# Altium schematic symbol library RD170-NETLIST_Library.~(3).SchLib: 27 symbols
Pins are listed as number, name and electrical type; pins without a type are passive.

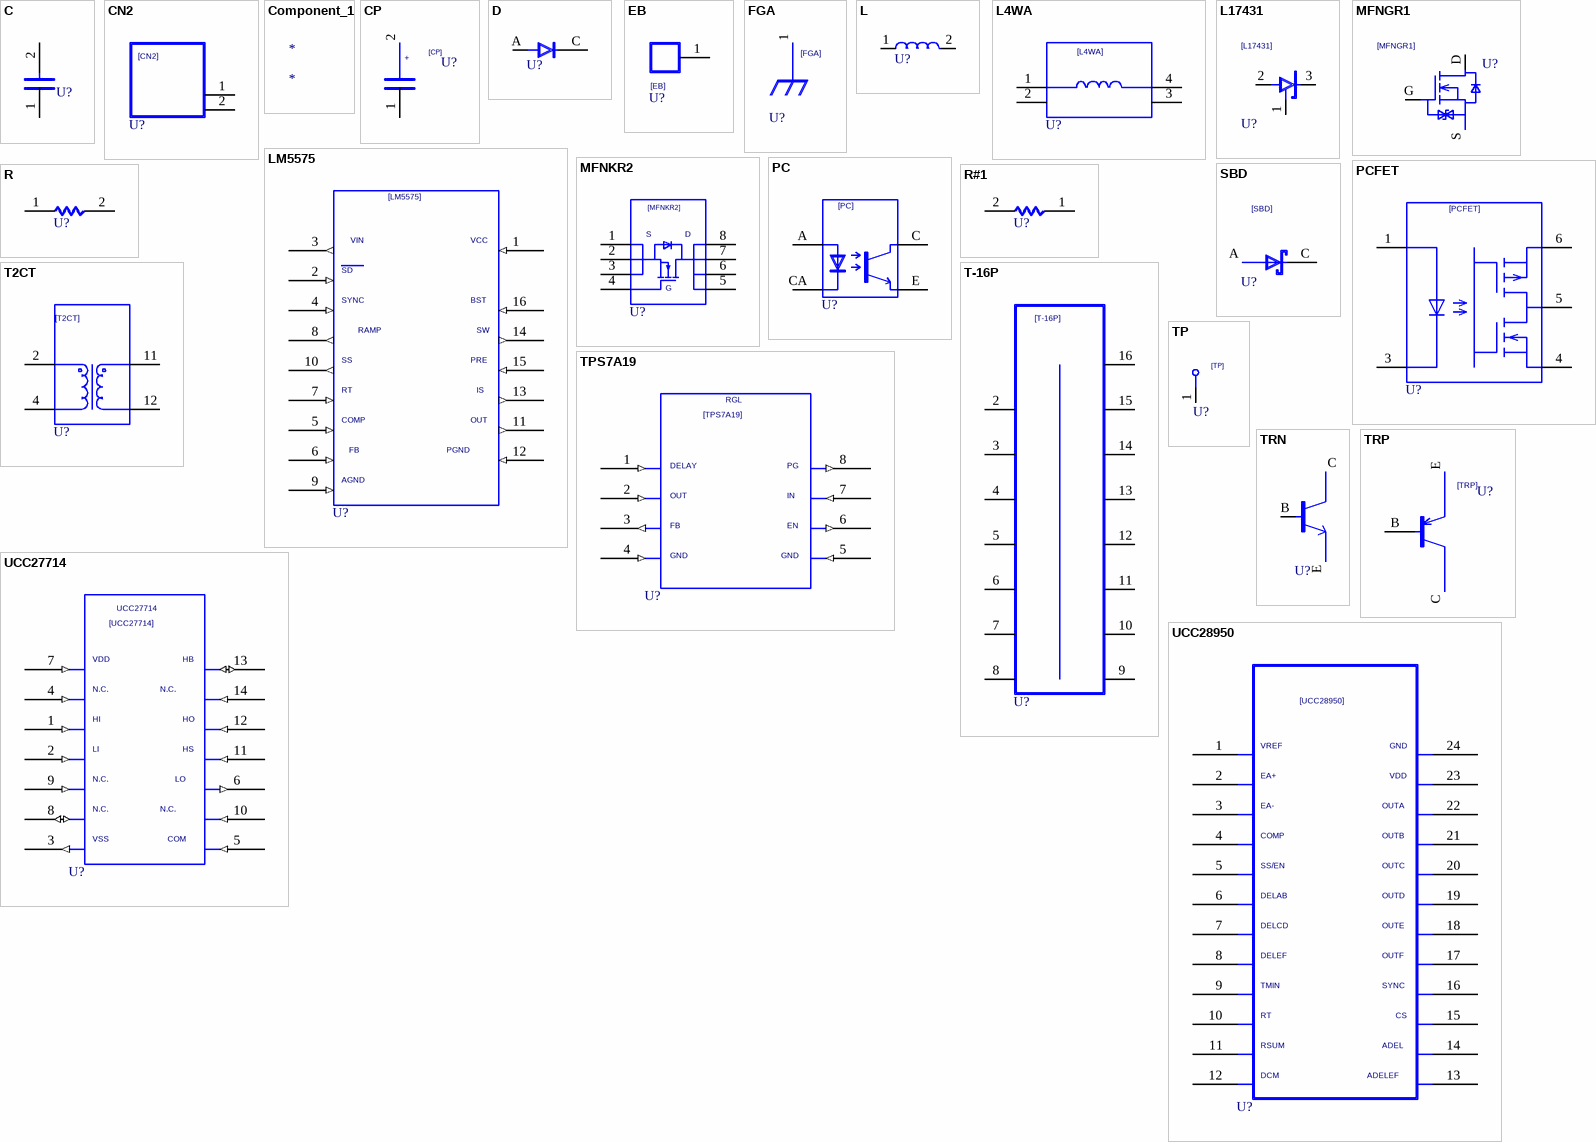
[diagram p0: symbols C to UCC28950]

## C
designator U?  (value not drawn)
OriginalSymbolOrigin: (2540,7620); Altium-Right: 20; Altium-Bottom: 10
pins: 1, 2

## CN2
designator U?  (value not drawn)
OriginalSymbolOrigin: (2540,15240); Altium-Right: 50; Altium-Bottom: 60
pins: 1, 2

## Component_1
designator *

## CP
designator U?  (value not drawn)
OriginalSymbolOrigin: (2540,12700); Altium-Right: 20; Altium-Bottom: 30
pins: 1, 2

## D
designator U?  (value not drawn)
SAVEAREA0: -565,-171,12979,8058; SAVECOUNT: 1; OriginalSymbolOrigin: (2540,5080); Altium-Right: 20
pins: A, C

## EB
designator U?  (value not drawn)
OriginalSymbolOrigin: (2540,12700); Altium-Right: 20
pins: 1

## FGA
designator U?  (value not drawn)
OriginalSymbolOrigin: (0,10160); Altium-Right: 30; Altium-Bottom: 40
pins: 1

## L
designator U?  (value not drawn)
OriginalSymbolOrigin: (2540,5080); Altium-Right: 30; Altium-Bottom: 20
pins: 1, 2

## L4WA
designator U?  (value not drawn)
SAVECOUNT: 10; SAVEAREA0: -2088,-30,30063,17749; TIME: 11:26:51; UPDATEUSER: q91866sr; UPDATETIME: 09:26:58; OriginalSymbolOrigin: (5080,15240); Altium-Right: 70; Altium-Bottom: 50
pins: 1, 2, 3, 4

## L17431
designator U?  (value not drawn)
OriginalSymbolOrigin: (2540,7620); Altium-Right: 20
pins: 1, 2, 3

## LM5575
designator U?  (value not drawn)
SAVECOUNT: 74; SAVEAREA0: -22463,-689,65805,66700; TIME: 14:20:25; UPDATEUSER: q91866sr; UPDATETIME: 16:21:18; OriginalSymbolOrigin: (7620,60960); Altium-Right: 110; Altium-Bottom: 210
pins: 1 (in), 2 (in), 3 (out), 4 (in), 5 (in), 6 (in), 7 (in), 8 (out), 9 (in), 10 (out), 11 (out), 12 (in), 13 (out), 14 (out), 15 (in), 16 (in)

## MFNGR1
designator U?  (value not drawn)
SAVECOUNT: 24; SAVEAREA0: -14204,-8572,26849,21288; TIME: 16:49:03; UPDATEUSER: ikeda-k; UPDATETIME: 18:49:38; OriginalSymbolOrigin: (2540,10160); Altium-Right: 40
pins: D, G, S

## MFNKR2
designator U?  (value not drawn)
SAVEAREA0: -9199,-39,32138,22820; TIME: 18:57:44; UPDATEUSER: q91866sr; UPDATETIME: 12:36:02; SAVECOUNT: 10; OriginalSymbolOrigin: (5080,20320); Altium-Right: 50; Altium-Bottom: 70
pins: 1, 2, 3, 4, 5, 6, 7, 8

## PC
designator U?  (value not drawn)
OriginalSymbolOrigin: (5080,17780); Altium-Right: 50; Altium-Bottom: 70
pins: A, C, CA, E

## PCFET
designator U?  (value not drawn)
TIME: 11:37:10; UPDATEUSER: q91866sr; UPDATETIME: 16:31:08; SAVECOUNT: 14; SAVEAREA0: -7234,-371,40293,35914; OriginalSymbolOrigin: (5080,33020); Altium-Right: 90; Altium-Bottom: 120
pins: 1, 3, 4, 5, 6

## R
designator U?  (value not drawn)
OriginalSymbolOrigin: (5080,5080); Altium-Right: 20
pins: 1, 2

## R#1
designator U?, comment R  (value not drawn)
OriginalSymbolOrigin: (5080,5080); Altium-Right: 20
pins: 1 2, 2 1

## SBD
designator U?  (value not drawn)
OriginalSymbolOrigin: (0,5080); Altium-Right: 30; Altium-Bottom: 20
pins: A, C

## T2CT
designator U?  (value not drawn)
TIME: 18:03:00; UPDATEUSER: q91866sr; SAVECOUNT: 2; SAVEAREA0: -11493,-43,34436,25356; OriginalSymbolOrigin: (5080,22860); Altium-Right: 50; Altium-Bottom: 80
pins: 2, 4, 11, 12

## T-16P
designator U?  (value not drawn)
SAVEAREA0: -36922,-744,61114,73099; SAVECOUNT: 21; TIME: 15:53:21; UPDATEUSER: CR5000; UPDATETIME: 16:11:03; OriginalSymbolOrigin: (5080,68580); Altium-Right: 60; Altium-Bottom: 260
pins: 2, 3, 4, 5, 6, 7, 8, 9, 10, 11, 12, 13, 14, 15, 16

## TP
designator U?  (value not drawn)
OriginalSymbolOrigin: (0,7620); Altium-Right: 20
pins: 1

## TPS7A19
designator U?  (value not drawn)
SAVEAREA0: 0,-963,45720,33942; SAVECOUNT: 69; TIME: 14:04:55; UPDATEUSER: q91866sr; UPDATETIME: 17:23:08; OriginalSymbolOrigin: (7620,33020); Altium-Right: 120; Altium-Bottom: 130
pins: 1 (in), 2 (in), 3 (out), 4 (in), 5 (in), 6 (out), 7 (in), 8 (out)

## TRN
designator U?  (value not drawn)
OriginalSymbolOrigin: (2540,17780); Altium-Right: 20; Altium-Bottom: 80
pins: B, C, E

## TRP
designator U?  (value not drawn)
OriginalSymbolOrigin: (5080,22860); Altium-Right: 20; Altium-Bottom: 100
pins: B, C, E

## UCC27714
designator U?  (value not drawn)
PARTS: 1; SAVECOUNT: 17; SAVEAREA0: -35169,11388,76116,57108; TIME: 14:04:55; UPDATEUSER: q91866sr; UPDATETIME: 16:48:45; DEVICENAME: 74HC244AF; DEVICE: 74VHC245; PKG_TYPE: 20PIN; LEVEL: STD; HETERO: 74VHC245,74VHC245_P; OriginalSymbolOrigin: (7620,45720); Altium-Right: 100; Altium-Bottom: 180
pins: 1 (in), 2 (in), 3 (out), 4 (in), 5 (in), 6 (out), 7 (in), 8 (io), 9 (in), 10 (in), 11 (in), 12 (in), 13 (io), 14 (in)

## UCC28950
designator U?  (value not drawn)
SAVECOUNT: 69; SAVEAREA0: -101871,-17388,148743,93366; TIME: 18:25:15; UPDATEUSER: S.Itagaki; UPDATETIME: 11:59:25; OriginalSymbolOrigin: (7620,76200); Altium-Right: 130; Altium-Bottom: 290
pins: 1, 2, 3, 4, 5, 6, 7, 8, 9, 10, 11, 12, 13, 14, 15, 16, 17, 18, 19, 20, 21, 22, 23, 24

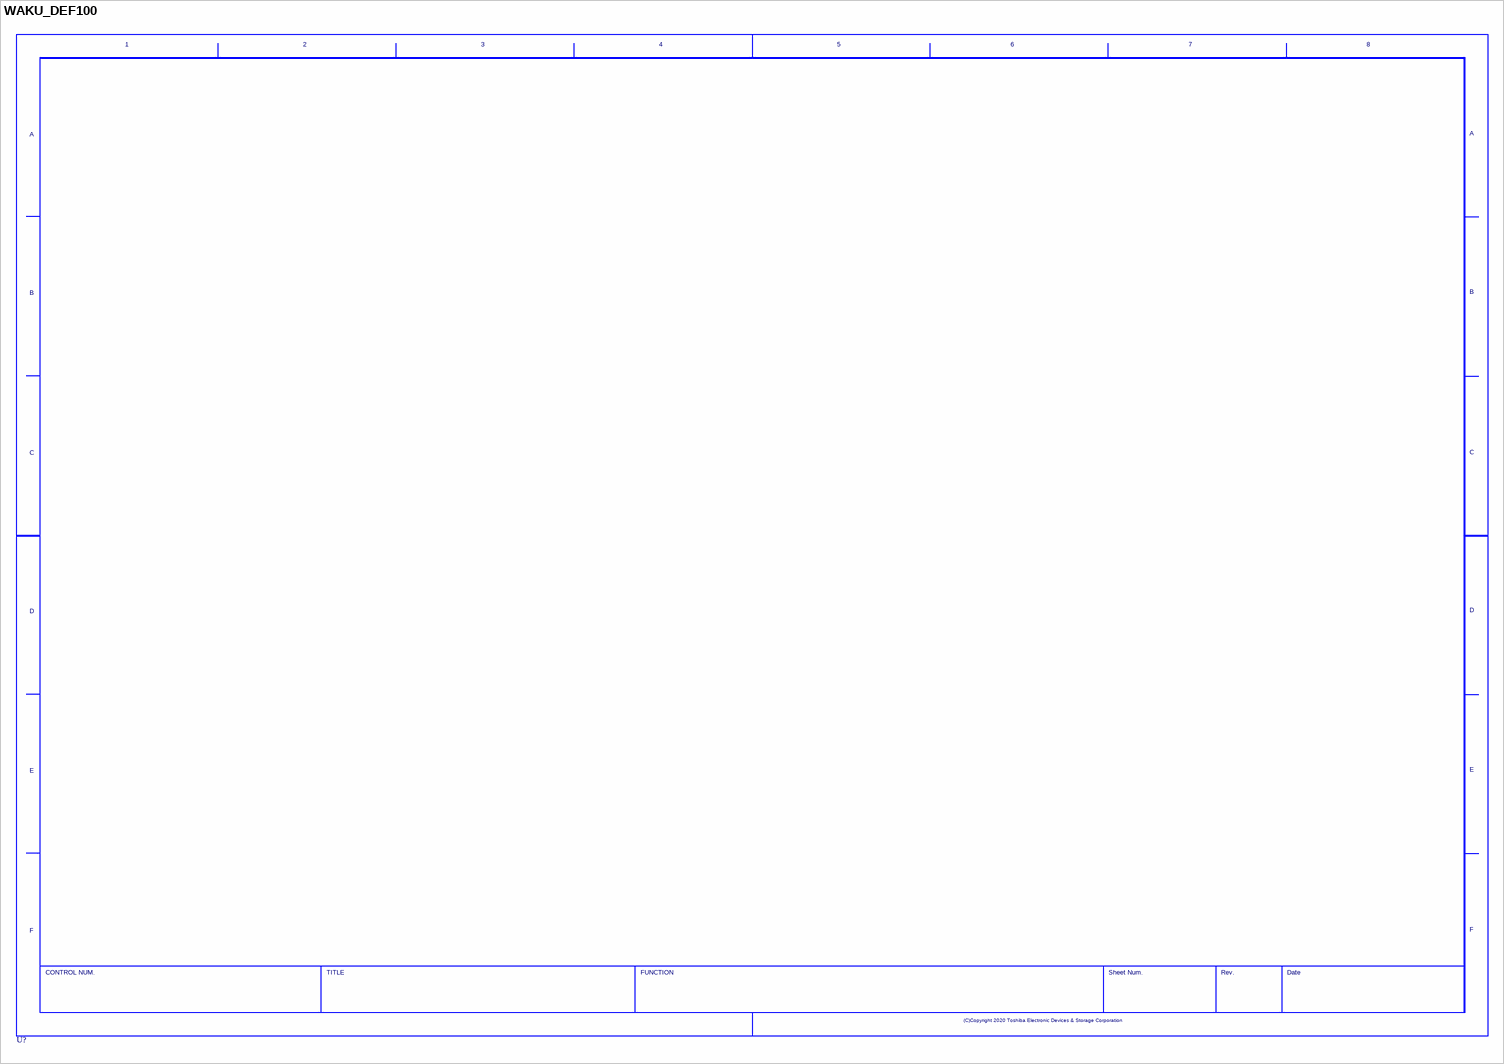
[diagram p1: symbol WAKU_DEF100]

## WAKU_DEF100
designator U?  (value not drawn)
PLOTTIME: HH:MM; SAVEAREA0: 218350,-40131,416688,63935; TIME: 14:30:25; UPDATEUSER: t5459927; UPDATETIME: 08:40:07; SAVECOUNT: 5; OriginalSymbolOrigin: (10160,284480); Altium-Right: 1570; Altium-Bottom: 1070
